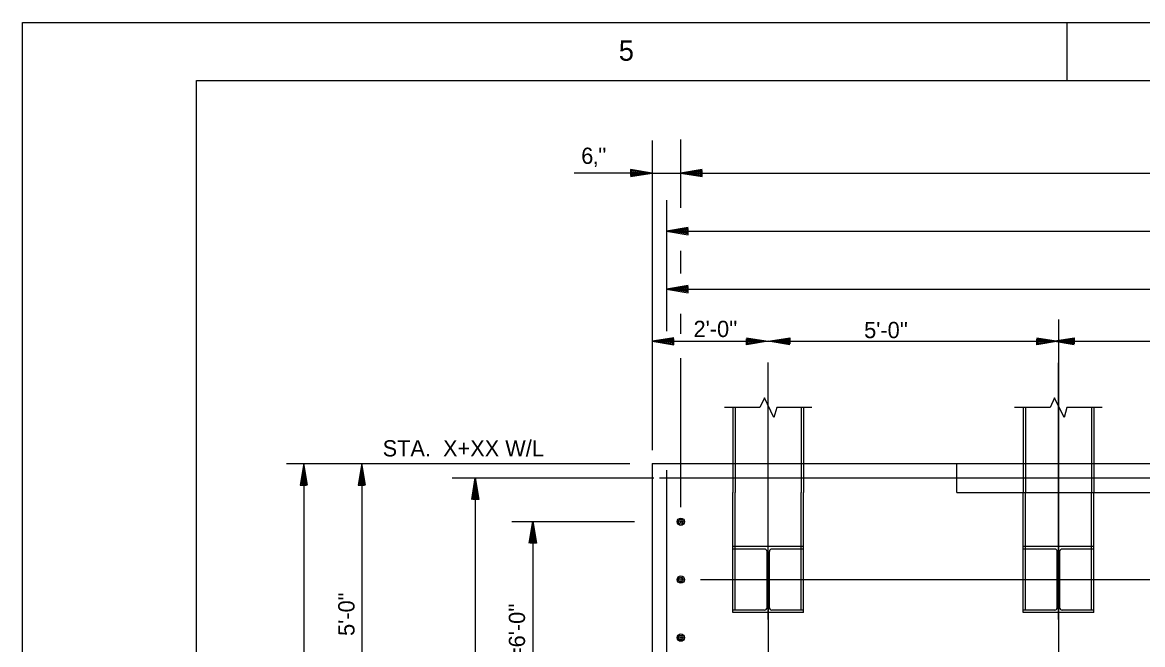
# Model space of a CAD drawing. Extents: x -11983 to -11903, y -13969.5 to -13913.5.
# Drawn here: x -11983.01 to -11963.71, y -13924.19 to -13913.48 of the extents above; entities that cross this region are included whole.
import ezdxf

# ---------------------------------------------------------------- set-up
doc = ezdxf.new("R2010")
doc.units = 0
for name, color, linetype in [('Level 1', 7, 'Continuous'), ('Level 2', 7, 'Continuous'), ('Level 22', 7, 'Continuous'), ('Level 3', 7, 'Continuous'), ('Level 50', 7, 'Continuous'), ('Level 6', 7, 'Continuous')]:
    doc.layers.add(name, color=color, linetype=linetype)

msp = doc.modelspace()

# ---------------------------------------------------------------- linework, layer by layer
at = {"layer": 'Level 1'}
msp.add_line((-11965.012, -13914.481), (-11965.012, -13913.481), dxfattribs=at)
for points in [[(-11983.012, -13913.481), (-11903.012, -13913.481), (-11903.012, -13969.481), (-11983.012, -13969.481)], [(-11980.012, -13914.481), (-11904.012, -13914.481), (-11904.012, -13968.481), (-11980.012, -13968.481)]]:
    msp.add_lwpolyline(points, close=True, dxfattribs=at)
at = {"layer": 'Level 2'}
for p, q in [((-11970.229, -13919.945), (-11970.309, -13920.113)), ((-11970.066, -13920.282), (-11970.229, -13919.945)), ((-11965.229, -13919.945), (-11965.309, -13920.113)), ((-11965.066, -13920.282), (-11965.229, -13919.945)), ((-11970.309, -13920.113), (-11970.919, -13920.113)), ((-11970.773, -13920.113), (-11970.773, -13921.573)), ((-11970.731, -13920.113), (-11970.731, -13921.573)), ((-11970.018, -13920.113), (-11970.066, -13920.282)), ((-11969.41, -13920.113), (-11970.018, -13920.113)), ((-11969.596, -13920.113), (-11969.596, -13921.573)), ((-11969.554, -13920.113), (-11969.554, -13921.573)), ((-11965.309, -13920.113), (-11965.919, -13920.113)), ((-11965.773, -13920.113), (-11965.773, -13921.573)), ((-11965.731, -13920.113), (-11965.731, -13921.573)), ((-11965.018, -13920.113), (-11965.066, -13920.282)), ((-11964.41, -13920.113), (-11965.018, -13920.113)), ((-11964.596, -13920.113), (-11964.596, -13921.573)), ((-11964.554, -13920.113), (-11964.554, -13921.573)), ((-11972.163, -13921.074), (-11972.163, -13929.066)), ((-11972.163, -13921.074), (-11957.178, -13921.074)), ((-11966.915, -13921.573), (-11966.915, -13921.074)), ((-11970.773, -13923.6), (-11970.773, -13921.573)), ((-11970.731, -13923.6), (-11970.731, -13921.573)), ((-11969.596, -13923.6), (-11969.596, -13921.573)), ((-11969.554, -13923.6), (-11969.554, -13921.573)), ((-11966.915, -13921.573), (-11957.178, -13921.573)), ((-11965.773, -13923.6), (-11965.773, -13921.573)), ((-11965.731, -13923.6), (-11965.731, -13921.573)), ((-11964.596, -13923.6), (-11964.596, -13921.573)), ((-11964.554, -13923.6), (-11964.554, -13921.573)), ((-11969.554, -13922.506), (-11970.773, -13922.506)), ((-11970.773, -13922.548), (-11970.773, -13922.506)), ((-11969.554, -13922.548), (-11969.554, -13922.506)), ((-11964.554, -13922.506), (-11965.773, -13922.506)), ((-11965.773, -13922.548), (-11965.773, -13922.506)), ((-11964.554, -13922.548), (-11964.554, -13922.506)), ((-11970.226, -13922.548), (-11970.773, -13922.548)), ((-11970.184, -13923.558), (-11970.184, -13922.59)), ((-11970.142, -13923.558), (-11970.142, -13922.59)), ((-11969.554, -13922.548), (-11970.101, -13922.548)), ((-11965.226, -13922.548), (-11965.773, -13922.548)), ((-11965.184, -13923.558), (-11965.184, -13922.59)), ((-11965.142, -13923.558), (-11965.142, -13922.59)), ((-11964.554, -13922.548), (-11965.101, -13922.548)), ((-11970.226, -13923.6), (-11970.773, -13923.6)), ((-11970.773, -13923.642), (-11970.773, -13923.6)), ((-11969.554, -13923.642), (-11970.773, -13923.642)), ((-11969.554, -13923.6), (-11970.101, -13923.6)), ((-11969.554, -13923.642), (-11969.554, -13923.6)), ((-11965.226, -13923.6), (-11965.773, -13923.6)), ((-11965.773, -13923.642), (-11965.773, -13923.6)), ((-11964.554, -13923.642), (-11965.773, -13923.642)), ((-11964.554, -13923.6), (-11965.101, -13923.6)), ((-11964.554, -13923.642), (-11964.554, -13923.6))]:
    msp.add_line(p, q, dxfattribs=at)
for centre, start, end in [((-11970.226, -13922.59), 0, 90), ((-11970.101, -13922.59), 90, 180), ((-11965.226, -13922.59), 0, 90), ((-11965.101, -13922.59), 90, 180), ((-11970.226, -13923.558), 270, 0), ((-11970.101, -13923.558), 180, 270), ((-11965.226, -13923.558), 270, 0), ((-11965.101, -13923.558), 180, 270)]:
    msp.add_arc(centre, 0.0417, start, end, dxfattribs=at)
at = {"layer": 'Level 22'}
for p, q in [((-11975.21, -13921.321), (-11975.21, -13928.814)), ((-11974.22, -13922.074), (-11974.22, -13928.074)), ((-11970.163, -13923.074), (-11970.163, -13922.282)), ((-11965.163, -13923.074), (-11965.163, -13922.282)), ((-11970.163, -13923.762), (-11970.163, -13923.074)), ((-11965.163, -13923.762), (-11965.163, -13923.074))]:
    msp.add_line(p, q, dxfattribs=at)
at = {"layer": 'Level 3'}
for p, q in [((-11972.163, -13915.517), (-11972.163, -13920.848)), ((-11971.677, -13915.496), (-11971.677, -13916.671)), ((-11972.163, -13916.074), (-11973.507, -13916.074)), ((-11972.329, -13916.074), (-11971.502, -13916.074)), ((-11972.267, -13916.074), (-11972.267, -13916.074)), ((-11972.163, -13916.074), (-11972.163, -13916.074)), ((-11971.677, -13916.074), (-11957.178, -13916.074)), ((-11971.677, -13916.074), (-11971.677, -13916.074)), ((-11971.573, -13916.074), (-11971.573, -13916.074)), ((-11971.914, -13916.54), (-11971.914, -13918.797)), ((-11971.914, -13917.074), (-11957.178, -13917.074)), ((-11971.914, -13917.074), (-11971.914, -13917.074)), ((-11971.81, -13917.074), (-11971.81, -13917.074)), ((-11971.677, -13917.411), (-11971.677, -13917.802)), ((-11971.914, -13918.074), (-11957.178, -13918.074)), ((-11971.914, -13918.074), (-11971.914, -13918.074)), ((-11971.81, -13918.074), (-11971.81, -13918.074)), ((-11971.677, -13918.498), (-11971.677, -13918.842)), ((-11965.163, -13918.594), (-11965.163, -13923.074)), ((-11972.163, -13918.971), (-11970.163, -13918.971)), ((-11970.163, -13918.971), (-11965.163, -13918.971)), ((-11965.163, -13918.971), (-11960.163, -13918.971)), ((-11971.677, -13919.26), (-11971.677, -13921.825)), ((-11970.163, -13923.074), (-11970.163, -13919.334)), ((-11970.163, -13923.594), (-11970.163, -13919.344)), ((-11970.163, -13923.074), (-11970.163, -13919.344)), ((-11970.163, -13923.074), (-11970.163, -13919.344)), ((-11970.163, -13923.074), (-11970.163, -13919.37)), ((-11965.163, -13923.594), (-11965.163, -13919.344)), ((-11965.163, -13923.074), (-11965.163, -13919.344)), ((-11965.163, -13923.074), (-11965.163, -13919.344)), ((-11965.163, -13923.074), (-11965.163, -13919.37)), ((-11978.464, -13921.074), (-11972.547, -13921.074)), ((-11978.163, -13921.074), (-11978.163, -13929.066)), ((-11978.163, -13921.074), (-11978.163, -13921.074)), ((-11977.163, -13921.074), (-11977.163, -13926.07)), ((-11977.163, -13921.074), (-11977.163, -13921.074)), ((-11978.163, -13921.178), (-11978.163, -13921.178)), ((-11977.163, -13921.178), (-11977.163, -13921.178)), ((-11975.609, -13921.321), (-11972.132, -13921.321)), ((-11974.581, -13922.074), (-11972.465, -13922.074)), ((-11971.331, -13923.074), (-11960.163, -13923.074)), ((-11970.163, -13923.074), (-11970.163, -13927.066)), ((-11965.163, -13923.074), (-11965.163, -13927.066))]:
    msp.add_line(p, q, dxfattribs=at)
for points in [[(-11972.537, -13916.136), (-11972.163, -13916.074), (-11972.537, -13916.012), (-11972.537, -13916.118), (-11972.267, -13916.074), (-11972.521, -13916.032), (-11972.521, -13916.1), (-11972.367, -13916.074), (-11972.505, -13916.052), (-11972.505, -13916.08), (-11972.471, -13916.074)], [(-11971.303, -13916.012), (-11971.677, -13916.074), (-11971.303, -13916.136), (-11971.303, -13916.03), (-11971.573, -13916.074), (-11971.319, -13916.116), (-11971.319, -13916.048), (-11971.473, -13916.074), (-11971.335, -13916.096), (-11971.335, -13916.068), (-11971.369, -13916.074)], [(-11971.54, -13917.012), (-11971.914, -13917.074), (-11971.54, -13917.136), (-11971.54, -13917.03), (-11971.81, -13917.074), (-11971.556, -13917.116), (-11971.556, -13917.048), (-11971.71, -13917.074), (-11971.572, -13917.096), (-11971.572, -13917.068), (-11971.606, -13917.074)], [(-11971.54, -13918.012), (-11971.914, -13918.074), (-11971.54, -13918.136), (-11971.54, -13918.03), (-11971.81, -13918.074), (-11971.556, -13918.116), (-11971.556, -13918.048), (-11971.71, -13918.074), (-11971.572, -13918.096), (-11971.572, -13918.068), (-11971.606, -13918.074)], [(-11978.101, -13921.448), (-11978.163, -13921.074), (-11978.225, -13921.448), (-11978.119, -13921.448), (-11978.163, -13921.178), (-11978.205, -13921.432), (-11978.137, -13921.432), (-11978.163, -13921.278), (-11978.185, -13921.416), (-11978.157, -13921.416), (-11978.163, -13921.382)], [(-11977.101, -13921.448), (-11977.163, -13921.074), (-11977.225, -13921.448), (-11977.119, -13921.448), (-11977.163, -13921.178), (-11977.205, -13921.432), (-11977.137, -13921.432), (-11977.163, -13921.278), (-11977.185, -13921.416), (-11977.157, -13921.416), (-11977.163, -13921.382)]]:
    msp.add_lwpolyline(points, dxfattribs=at)
at = {"layer": 'Level 50'}
for p, q in [((-11972.163, -13918.971), (-11972.163, -13918.971)), ((-11972.059, -13918.971), (-11972.059, -13918.971)), ((-11970.267, -13918.971), (-11970.267, -13918.971)), ((-11970.163, -13918.971), (-11970.163, -13918.971)), ((-11970.163, -13918.971), (-11970.163, -13918.971)), ((-11970.059, -13918.971), (-11970.059, -13918.971)), ((-11965.267, -13918.971), (-11965.267, -13918.971)), ((-11965.267, -13918.971), (-11965.267, -13918.971)), ((-11965.163, -13918.971), (-11965.163, -13918.971)), ((-11965.163, -13918.971), (-11965.163, -13918.971)), ((-11975.21, -13921.321), (-11975.21, -13921.321)), ((-11975.21, -13921.425), (-11975.21, -13921.425)), ((-11974.22, -13922.074), (-11974.22, -13922.074)), ((-11974.22, -13922.178), (-11974.22, -13922.178))]:
    msp.add_line(p, q, dxfattribs=at)
for points in [[(-11971.789, -13918.909), (-11972.163, -13918.971), (-11971.789, -13919.033), (-11971.789, -13918.927), (-11972.059, -13918.971), (-11971.805, -13919.013), (-11971.805, -13918.945), (-11971.959, -13918.971), (-11971.821, -13918.993), (-11971.821, -13918.965), (-11971.855, -13918.971)], [(-11970.537, -13918.909), (-11970.163, -13918.971), (-11970.537, -13919.033), (-11970.537, -13918.927), (-11970.267, -13918.971), (-11970.521, -13919.013), (-11970.521, -13918.945), (-11970.367, -13918.971), (-11970.505, -13918.993), (-11970.505, -13918.965), (-11970.471, -13918.971)], [(-11969.789, -13919.033), (-11970.163, -13918.971), (-11969.789, -13918.909), (-11969.789, -13919.015), (-11970.059, -13918.971), (-11969.805, -13918.929), (-11969.805, -13918.997), (-11969.959, -13918.971), (-11969.821, -13918.949), (-11969.821, -13918.977), (-11969.855, -13918.971)], [(-11965.537, -13918.909), (-11965.163, -13918.971), (-11965.537, -13919.033), (-11965.537, -13918.927), (-11965.267, -13918.971), (-11965.521, -13919.013), (-11965.521, -13918.945), (-11965.367, -13918.971), (-11965.505, -13918.993), (-11965.505, -13918.965), (-11965.471, -13918.971)], [(-11964.893, -13919.033), (-11965.267, -13918.971), (-11964.893, -13918.909), (-11964.893, -13919.015), (-11965.163, -13918.971), (-11964.909, -13918.929), (-11964.909, -13918.997), (-11965.063, -13918.971), (-11964.925, -13918.949), (-11964.925, -13918.977), (-11964.959, -13918.971)], [(-11975.272, -13921.695), (-11975.21, -13921.321), (-11975.148, -13921.695), (-11975.254, -13921.695), (-11975.21, -13921.425), (-11975.168, -13921.679), (-11975.236, -13921.679), (-11975.21, -13921.525), (-11975.188, -13921.663), (-11975.216, -13921.663), (-11975.21, -13921.629)], [(-11974.282, -13922.448), (-11974.22, -13922.074), (-11974.158, -13922.448), (-11974.264, -13922.448), (-11974.22, -13922.178), (-11974.178, -13922.432), (-11974.246, -13922.432), (-11974.22, -13922.278), (-11974.198, -13922.416), (-11974.226, -13922.416), (-11974.22, -13922.382)]]:
    msp.add_lwpolyline(points, dxfattribs=at)
at = {"layer": 'Level 6'}
for p, q in [((-11972.035, -13921.324), (-11957.178, -13921.324)), ((-11971.914, -13921.193), (-11971.914, -13928.927))]:
    msp.add_line(p, q, dxfattribs=at)
for centre, radius in [((-11971.67, -13922.078), 0.0633), ((-11971.67, -13922.078), 0.0396), ((-11971.67, -13922.078), 0.0158), ((-11971.67, -13923.074), 0.0633), ((-11971.67, -13923.074), 0.0396), ((-11971.67, -13923.074), 0.0158), ((-11971.67, -13924.074), 0.0633), ((-11971.67, -13924.074), 0.0396), ((-11971.67, -13924.074), 0.0158)]:
    msp.add_circle(centre, radius, dxfattribs=at)

# ---------------------------------------------------------------- texts
at = {"layer": 'Level 1'}
msp.add_text('5', height=0.351, dxfattribs=at).set_placement((-11972.738, -13914.141))
at = {"layer": 'Level 3'}
for s, p in [("6‚'' ", (-11973.385, -13915.917)), ("2'-0'' ", (-11971.45, -13918.898)), ("5'-0''", (-11968.511, -13918.917)), ('STA.  X+XX W/L', (-11976.806, -13920.954))]:
    msp.add_text(s, height=0.28, dxfattribs=at).set_placement(p)
for s, p in [('5\'-0"', (-11977.291, -13924.044)), ("#4 DOWELS AT 12''=6'-0''", (-11974.353, -13927.849))]:
    msp.add_text(s, height=0.28, rotation=90, dxfattribs=at).set_placement(p)

doc.saveas('drawing.dxf')
